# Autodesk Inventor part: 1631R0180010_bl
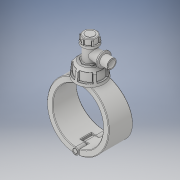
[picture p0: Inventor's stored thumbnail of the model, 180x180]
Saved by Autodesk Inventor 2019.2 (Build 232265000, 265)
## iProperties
Created: 2022-02
Part Number: 1631R0180010_bl
Material: Generic
Description: Plassadle Tapper Male 180x1''
Document SubType Name: Modeling
Designer: comp2
Density: 1 g/cm^3
Appearance: Default
Author: comp2
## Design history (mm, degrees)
derived "1631R.ipt"
feature "Solid1::1631R.ipt" dims "ScaleForDerivedMember" = 10
feature "Solid2::1631R.ipt" dims "ScaleForDerivedMember" = 10
feature "Solid3::1631R.ipt" dims "ScaleForDerivedMember" = 10
feature "Solid4::1631R.ipt" dims "ScaleForDerivedMember" = 10
tag "TaggingFeature1"
body "Solid1"
body "Solid2"
body "Solid3"
body "Solid4"
other parameters: "d7" = 209 [user parameter], "d8" = 85 deg [user parameter], "d9" = 45 deg [user parameter], "d10" = 102 [user parameter], "d11" = 52 [user parameter], "d12" = 36.4 [user parameter], "d13" = 42.84 [user parameter], "d14" = 57.936 [user parameter], "d15" = 2.6 [user parameter], "d16" = 2 [user parameter], "d17" = 2 [user parameter], "d18" = 31.2 [user parameter], "d19" = 7.8 [user parameter], "d20" = 1 [user parameter], "d21" = 30.6 [user parameter], "d22" = 1 [user parameter], "d23" = 15.6 [user parameter], "d24" = 78 [user parameter], "d27" = 144 [user parameter], "d29" = 49.8735 [user parameter], "d31" = 33.249 [user parameter], "d32" = 31.2 [user parameter], "d33" = 26.52 [user parameter], "d41" = 5 [user parameter], "d42" = 4 [user parameter], "d46" = 56.1 [user parameter], "d47" = 36.5739 [user parameter], "d48" = 52 [user parameter], "d49" = 4.4 [user parameter], "d51" = 0 [user parameter], "d52" = 28 [user parameter], "d53" = 121 [user parameter], "d54" = 38.5 [user parameter], "d55" = 0 [user parameter], "d56" = 22 [user parameter], "d57" = 22 [user parameter], "d59" = 0 [user parameter], "d61" = 0 [user parameter], "d62" = 38.5 [user parameter], "d63" = 0 [user parameter], "d65" = 0 [user parameter], "d67" = 0 [user parameter], "d69" = 0 [user parameter], "d70" = 1 [user parameter], "d71" = 105.6 [user parameter], "d72" = 0 [user parameter], "d73" = 2 [user parameter], "d77" = 24.93675 [user parameter], "d78" = 86.7 [user parameter], "d79" = 5.1 [user parameter], "d80" = 60 deg [user parameter], "d81" = 5.1 [user parameter], "d84" = 0 [user parameter], "d85" = 1 [user parameter], "d87" = 360 deg [user parameter], "d90" = 0 [user parameter], "d91" = 1 [user parameter], "d93" = 60 deg [user parameter], "d94" = 3.06 [user parameter], "d95" = 3.06 [user parameter], "d97" = 0 [user parameter], "d98" = 0.5 [user parameter], "d100" = 360 deg [user parameter], "d102" = 2 [user parameter], "d117" = 0.5 [user parameter], "d118" = 31.2 [user parameter], "d119" = 100 deg [user parameter], "d121" = 0 [user parameter], "d1" = 25 [user parameter], "E_" = 54 [user parameter], "E1" = 102 [user parameter], "H2" = 144 [user parameter], "H3" = 78 [user parameter], "H_costum" = 52 [user parameter], "R" = 33.249 [user parameter]
